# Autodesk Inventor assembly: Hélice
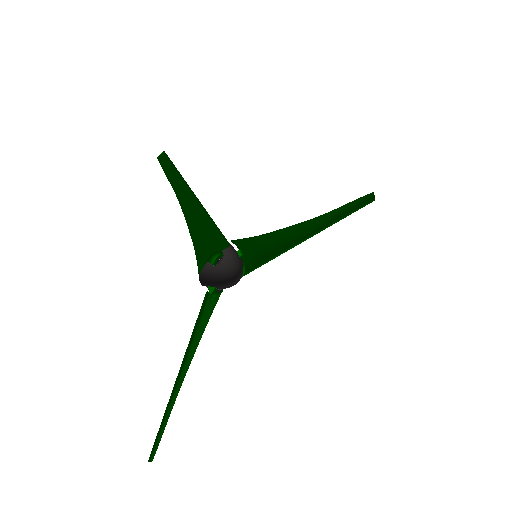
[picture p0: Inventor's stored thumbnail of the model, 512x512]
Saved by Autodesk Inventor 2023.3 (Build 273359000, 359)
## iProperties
Created: 2014-09
Part Number: Hélice
Document SubType Name: Assembly
Designer: papa
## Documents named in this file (7)
- C:\Travail\BTS TechCom\2-TechnoIndus\21-Meca\214-Systémes Industriels-SI\2141-Pièces Ecrites\21411-Cycle1\214112-TP02Eolienne\2141122-DossierTechniqueEolienne\21411223-Maquette numerique\CEC-Eolienne\Helice\Hélice.iam
- C:\Travail\BTS TechCom\2-TechnoIndus\21-Meca\214-Systémes Industriels-SI\2141-Pièces Ecrites\21411-Cycle1\214112-TP02Eolienne\2141122-DossierTechniqueEolienne\21411223-Maquette numerique\CEC-Eolienne\Helice\15-Moyeu.ipt
- C:\Travail\BTS TechCom\2-TechnoIndus\21-Meca\214-Systémes Industriels-SI\2141-Pièces Ecrites\21411-Cycle1\214112-TP02Eolienne\2141122-DossierTechniqueEolienne\21411223-Maquette numerique\CEC-Eolienne\Helice\16-Pâle.ipt
- C:\Travail\BTS TechCom\2-TechnoIndus\21-Meca\214-Systémes Industriels-SI\2141-Pièces Ecrites\21411-Cycle1\214112-TP02Eolienne\2141122-DossierTechniqueEolienne\21411223-Maquette numerique\CEC-Eolienne\Helice\17-Nez.ipt
- C:\Users\Thier\OneDrive\Documents\Inventor\Content Center Files\R2023\fr-FR\NF E 25-125\NF E 25-125 - M6 x 30.ipt
- C:\Travail\BTS TechCom\2-TechnoIndus\21-Meca\214-Systémes Industriels-SI\2141-Pièces Ecrites\21411-Cycle1\214112-TP02Eolienne\2141122-DossierTechniqueEolienne\21411223-Maquette numerique\CEC-Eolienne\Helice\23-Ecrou H FR M6, DIN 985.ipt
- C:\Travail\BTS TechCom\2-TechnoIndus\21-Meca\214-Systémes Industriels-SI\2141-Pièces Ecrites\21411-Cycle1\214112-TP02Eolienne\2141122-DossierTechniqueEolienne\21411223-Maquette numerique\CEC-Eolienne\Helice\22-Rondelle-ISO 7089 - 6 - 140 HV.ipt
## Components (14 placed, 6 different names)
1. moyeu:1 — Logement:1, Angle:1, Logement:2, Angle:2, Logement:3, Angle:3, Logement:5, Logement:6, Logement:7, Angle:4, Angle:5, Angle:6, Affleurement:3, Placage:2
2. pâle:1 — Logement:1, Angle:1
3. pâle:2 — Logement:3, Angle:3
4. pâle:3 — Logement:2, Angle:2, Placage:1
5. nez:1 — Placage:1, Affleurement:3, Placage:2
6. NF E 25-125 M6 x 30:1 — Logement:13
7. 23-Ecrou H FR M6, DIN 985:1 — Logement:7, Angle:4
8. 23-Ecrou H FR M6, DIN 985:2 — Logement:6, Angle:6
9. 23-Ecrou H FR M6, DIN 985:3 — Logement:5, Angle:5
10. NF E 25-125 M6 x 30:2 — Logement:12
11. NF E 25-125 M6 x 30:3 — Logement:11
12. ISO 7089 6:1 — Logement:12
13. ISO 7089 6:2 — Logement:13
14. ISO 7089 6:3 — Logement:11
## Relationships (18: Insert 9, Angle 6, Mate 2, Flush 1)
- Logement:1 [Insert]: moyeu:1 ↔ pâle:1
- Angle:1: moyeu:1 ↔ pâle:1
- Logement:2 [Insert]: moyeu:1 ↔ pâle:3
- Angle:2: moyeu:1 ↔ pâle:3
- Logement:3 [Insert]: moyeu:1 ↔ pâle:2
- Angle:3: moyeu:1 ↔ pâle:2
- Logement:5 [Insert]: moyeu:1 ↔ 23-Ecrou H FR M6, DIN 985:3
- Logement:6 [Insert]: moyeu:1 ↔ 23-Ecrou H FR M6, DIN 985:2
- Logement:7 [Insert]: moyeu:1 ↔ 23-Ecrou H FR M6, DIN 985:1
- Angle:4: moyeu:1 ↔ 23-Ecrou H FR M6, DIN 985:1
- Angle:5: moyeu:1 ↔ 23-Ecrou H FR M6, DIN 985:3
- Angle:6: moyeu:1 ↔ 23-Ecrou H FR M6, DIN 985:2
- Logement:11 [Insert]: NF E 25-125 M6 x 30:3 ↔ ISO 7089 6:3
- Logement:12 [Insert]: NF E 25-125 M6 x 30:2 ↔ ISO 7089 6:1
- Logement:13 [Insert]: NF E 25-125 M6 x 30:1 ↔ ISO 7089 6:2
- Placage:1 [Mate]: pâle:3 ↔ nez:1
- Affleurement:3 [Flush]: moyeu:1 ↔ nez:1
- Placage:2 [Mate]: moyeu:1 ↔ nez:1
